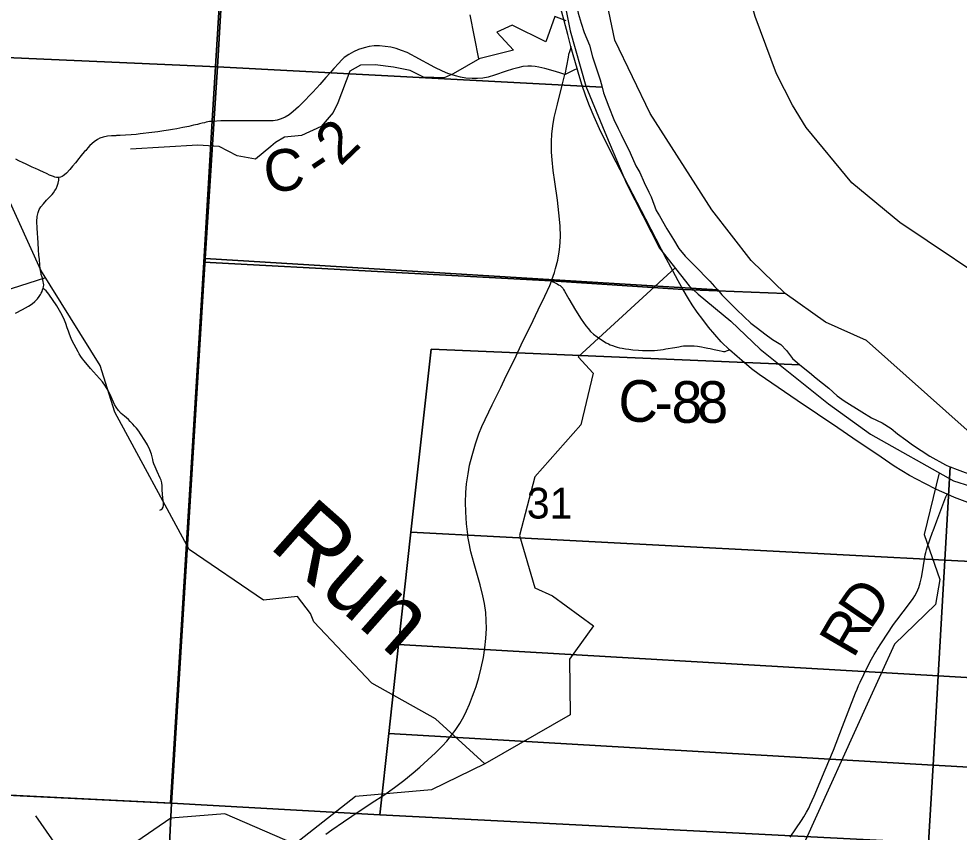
# Model space of a CAD drawing. Extents: x 0 to 34, y 0 to 22.
# Drawn here: x 5.797 to 7.078, y 15.893 to 17.002 of the extents above; entities that cross this region are included whole.
import ezdxf

# ---------------------------------------------------------------- set-up
doc = ezdxf.new("R2010")
doc.units = 0
for name, color, linetype in [('Default', 7, 'Continuous'), ('GM_X_County_Road', 7, 'Continuous'), ('GM_X_County_Road_Text', 7, 'Continuous'), ('GM_X_Interchange_Ramps', 7, 'Continuous'), ('GM_X_Major_River', 7, 'Continuous'), ('GM_X_Minor_River', 7, 'Continuous'), ('GM_X_Minor_River_Text', 7, 'Continuous'), ('GM_X_Section', 7, 'Continuous'), ('GM_X_Section_Text', 7, 'Continuous'), ('GM_X_State_Route', 7, 'Continuous'), ('GM_X_Township_Road', 7, 'Continuous'), ('SH_Text', 7, 'Continuous')]:
    doc.layers.add(name, color=color, linetype=linetype)

msp = doc.modelspace()

# ---------------------------------------------------------------- linework, layer by layer
at = {"layer": 'Default'}
for points in [[(3.9292, 16.0191), (4.6644, 15.9921), (4.9525, 15.9829), (5.4606, 15.953), (5.4699, 15.9536), (5.4787, 15.9537), (5.4884, 15.9532), (5.5007, 15.9519), (5.5038, 15.9516), (5.5088, 15.951), (5.5156, 15.9503), (5.5249, 15.9499), (5.5387, 15.9494), (5.5476, 15.9495), (5.5597, 15.9496), (5.5657, 15.9498), (5.5704, 15.951), (5.5736, 15.9525), (5.5744, 15.953), (5.6773, 15.9486), (6.0035, 15.9327), (6.0487, 16.67), (6.0603, 16.8624), (6.127, 17.9511)], [(6.127, 17.9511), (6.0603, 16.8624), (6.0487, 16.67), (6.5224, 16.6444), (6.7022, 16.6326), (6.841, 16.6271), (6.7947, 16.6724), (6.7412, 16.7413), (6.6572, 16.8728), (6.6092, 16.9726), (6.5665, 17.1768), (6.5499, 17.3472), (6.5502, 17.3673), (6.5359, 17.8831)], [(7.0892, 16.4411), (6.9521, 16.5634), (6.8963, 16.5881), (6.841, 16.6271), (6.7022, 16.6326), (6.5224, 16.6444), (6.0487, 16.67), (6.0035, 15.9327), (5.6773, 15.9486)]]:
    msp.add_lwpolyline(points, dxfattribs=at)
at = {"layer": 'GM_X_County_Road'}
for points in [[(6.5407, 16.926), (6.534, 16.9282), (6.5249, 16.9309), (6.5136, 16.9339), (6.5056, 16.9358), (6.5006, 16.9367), (6.4957, 16.9372), (6.4904, 16.9371), (6.4838, 16.9365), (6.477, 16.935), (6.4698, 16.9331), (6.4609, 16.9303), (6.4452, 16.9248), (6.4363, 16.9223), (6.4292, 16.9209), (6.4218, 16.9205), (6.4148, 16.9203), (6.4062, 16.9208), (6.3989, 16.922), (6.3917, 16.924), (6.3815, 16.9272), (6.3741, 16.9303), (6.3636, 16.9355), (6.3371, 16.9497), (6.3318, 16.9525), (6.326, 16.9556), (6.3181, 16.9587), (6.3111, 16.961), (6.3037, 16.9631), (6.2962, 16.9641), (6.2881, 16.9648), (6.281, 16.9647), (6.2741, 16.9638), (6.2675, 16.9623), (6.2597, 16.9597), (6.2529, 16.9567), (6.2464, 16.953), (6.2403, 16.9488), (6.2365, 16.9454), (6.2327, 16.9412), (6.2261, 16.9338), (6.2209, 16.928), (6.2151, 16.9215), (6.207, 16.9121), (6.2029, 16.9075), (6.1971, 16.9011), (6.1926, 16.8965), (6.1875, 16.8913), (6.1827, 16.8865), (6.178, 16.8817), (6.1708, 16.8754), (6.1651, 16.8708), (6.1599, 16.8676), (6.1544, 16.8652), (6.149, 16.8637), (6.1432, 16.8627), (6.1357, 16.8625), (6.1284, 16.8624), (6.1136, 16.8627), (6.1061, 16.8626), (6.097, 16.8626), (6.0914, 16.8627), (6.0821, 16.8625), (6.0772, 16.8625), (6.0722, 16.8624), (6.0605, 16.8619)], [(6.0605, 16.8619), (6.0594, 16.8618), (6.0566, 16.8616), (6.0543, 16.8611), (6.0521, 16.8606), (6.0496, 16.8601), (6.0467, 16.8593), (6.0431, 16.8584), (6.0401, 16.8576), (6.0377, 16.857), (6.035, 16.8565), (6.0317, 16.8557), (6.0286, 16.855), (6.0201, 16.8534), (6.0122, 16.8518), (6.0063, 16.8507), (6.0009, 16.8497), (5.9942, 16.8488), (5.9862, 16.8478), (5.9782, 16.8468), (5.9622, 16.8448), (5.9566, 16.8441), (5.9498, 16.8436), (5.942, 16.8431), (5.9349, 16.8426), (5.9299, 16.8425)], [(5.9299, 16.8425), (5.9288, 16.8424), (5.9231, 16.8422), (5.9176, 16.8418), (5.9117, 16.8405), (5.9071, 16.8389), (5.9039, 16.8373), (5.8994, 16.8342), (5.8936, 16.8288), (5.891, 16.8258), (5.888, 16.8223), (5.8863, 16.8207), (5.8835, 16.8175), (5.8815, 16.8152), (5.88, 16.8132), (5.8785, 16.8113), (5.874, 16.8056), (5.8701, 16.8007), (5.8664, 16.7965), (5.8617, 16.7915), (5.859, 16.789), (5.8572, 16.7877), (5.8557, 16.7867), (5.8535, 16.7858), (5.8514, 16.7855), (5.8501, 16.7853), (5.8481, 16.7855), (5.8456, 16.786), (5.8438, 16.7867), (5.8386, 16.7887), (5.8352, 16.7902), (5.8295, 16.7929), (5.8262, 16.7944), (5.8234, 16.7958), (5.8194, 16.7976), (5.8149, 16.7997), (5.8104, 16.8019), (5.8058, 16.804), (5.8025, 16.8056), (5.7969, 16.8083), (5.7925, 16.8105)], [(5.792, 16.6003), (5.8018, 16.6056), (5.8101, 16.6101), (5.8148, 16.6132), (5.8187, 16.6163), (5.8222, 16.6199), (5.8244, 16.623), (5.8265, 16.626), (5.8274, 16.6276), (5.8285, 16.6301), (5.8292, 16.6322), (5.8298, 16.6344), (5.8303, 16.6365), (5.8306, 16.6391), (5.8302, 16.6415), (5.8298, 16.6434), (5.8293, 16.6462), (5.8284, 16.6496), (5.8274, 16.6533), (5.827, 16.6547), (5.8266, 16.6564), (5.8263, 16.6586), (5.826, 16.661), (5.8253, 16.6664), (5.8247, 16.6736), (5.8241, 16.6796), (5.8237, 16.6867), (5.823, 16.6962), (5.8217, 16.7164), (5.8214, 16.7256), (5.8218, 16.7323), (5.8229, 16.7376), (5.8246, 16.7418), (5.8266, 16.7452), (5.8302, 16.7497), (5.8346, 16.7543), (5.84, 16.7598), (5.8421, 16.7623), (5.844, 16.7646), (5.846, 16.7676), (5.8475, 16.7699), (5.8491, 16.7734), (5.8504, 16.7775), (5.8511, 16.7819), (5.8514, 16.7855)], [(6.5226, 16.6439), (6.5276, 16.6417), (6.5304, 16.6404), (6.5323, 16.6393), (6.5344, 16.638), (6.5362, 16.6365), (6.538, 16.6344), (6.5392, 16.6326), (6.5404, 16.6306), (6.5464, 16.6202), (6.5555, 16.6045), (6.5632, 16.5923), (6.5664, 16.5876), (6.5695, 16.5832), (6.5726, 16.5794), (6.576, 16.5757), (6.5802, 16.5719), (6.5851, 16.5681), (6.5922, 16.5631), (6.5973, 16.5601), (6.6004, 16.5585), (6.6029, 16.5574), (6.6059, 16.5562), (6.6093, 16.5549), (6.6124, 16.554), (6.6156, 16.5533), (6.6191, 16.5526), (6.6237, 16.5519), (6.6283, 16.5513), (6.6334, 16.5507), (6.6412, 16.5501), (6.6468, 16.5497), (6.6516, 16.5496), (6.6553, 16.5495), (6.6594, 16.5496), (6.6632, 16.5498), (6.6671, 16.5501), (6.6712, 16.5506), (6.675, 16.5511), (6.6784, 16.5517), (6.6909, 16.5538), (6.6964, 16.5548), (6.6997, 16.5554), (6.7028, 16.5558), (6.7058, 16.556), (6.709, 16.5561), (6.7128, 16.5561), (6.7171, 16.5558), (6.7219, 16.5553), (6.727, 16.5546), (6.7314, 16.5538), (6.7356, 16.553), (6.7391, 16.5522), (6.7446, 16.5509), (6.7512, 16.5494), (6.7553, 16.5485), (6.7572, 16.5483), (6.7593, 16.5484), (6.7614, 16.549), (6.7652, 16.5505)], [(7.0428, 16.304), (7.0479, 16.3176), (7.0604, 16.35), (7.0618, 16.3537)], [(6.8482, 15.8862), (6.8635, 15.9088), (6.8668, 15.9141), (6.8705, 15.9205), (6.8733, 15.926), (6.8755, 15.9305), (6.8807, 15.9424), (6.8956, 15.9779), (6.9073, 16.0051), (6.9194, 16.0372), (6.937, 16.0828), (6.9392, 16.0881), (6.9413, 16.093), (6.9433, 16.0975), (6.9532, 16.1184), (6.9587, 16.1289), (6.9624, 16.1353), (6.9646, 16.1391), (6.9666, 16.1422), (6.9723, 16.1511), (6.989, 16.1761), (6.9932, 16.1821), (7.0106, 16.2046), (7.0156, 16.2117), (7.0179, 16.2153), (7.0205, 16.2202), (7.0233, 16.2264), (7.0254, 16.2328), (7.0272, 16.24), (7.0285, 16.2479), (7.0312, 16.2651), (7.0321, 16.271), (7.0328, 16.2744), (7.0337, 16.2777), (7.0347, 16.2809), (7.0421, 16.302), (7.0428, 16.304)]]:
    msp.add_lwpolyline(points, dxfattribs=at)
at = {"layer": 'GM_X_Interchange_Ramps'}
msp.add_lwpolyline([(6.5493, 16.9638), (6.548, 16.9596), (6.5471, 16.9568), (6.5461, 16.9531), (6.5453, 16.9493), (6.5407, 16.926)], dxfattribs=at)
at = {"layer": 'GM_X_Major_River'}
for points in [[(6.4976, 17.8073), (6.4924, 17.6107), (6.4898, 17.5078), (6.4973, 17.4197), (6.5019, 17.3214), (6.514, 17.2114), (6.5258, 17.1009), (6.5409, 17.0216), (6.5482, 16.9852), (6.5697, 16.9098), (6.5979, 16.8416), (6.625, 16.7771), (6.67, 16.6892), (6.7102, 16.6378), (6.7228, 16.6264), (6.7671, 16.5894), (6.807, 16.5512), (6.9003, 16.4768), (6.9575, 16.4357), (7.0708, 16.372), (7.0939, 16.3645)], [(7.1477, 16.6232), (6.9976, 16.724), (6.932, 16.778), (6.87, 16.8537), (6.8514, 16.884), (6.8293, 16.9268), (6.8003, 17.0049), (6.7845, 17.0602), (6.7543, 17.1645), (6.7441, 17.2389), (6.7426, 17.2521), (6.7301, 17.3527), (6.7197, 17.489), (6.7149, 17.5588), (6.7178, 17.5835)]]:
    msp.add_lwpolyline(points, dxfattribs=at)
at = {"layer": 'GM_X_Minor_River'}
for points in [[(6.5429, 16.9987), (6.5271, 17.0046), (6.515, 16.9704), (6.4692, 16.9931), (6.4484, 16.9834), (6.4708, 16.959), (6.4235, 16.9471), (6.4121, 17.007)], [(6.4252, 16.9476), (6.3887, 16.9268), (6.3765, 16.9211), (6.3481, 16.9222), (6.3299, 16.931), (6.3072, 16.9359), (6.2825, 16.9389), (6.2624, 16.9385), (6.2477, 16.9305), (6.2313, 16.8871), (6.2253, 16.8738), (6.2086, 16.8548), (6.182, 16.8426), (6.1589, 16.8403), (6.1464, 16.8331), (6.14, 16.8277), (6.1191, 16.8106), (6.0945, 16.8148), (6.0698, 16.8277), (6.0406, 16.8295), (5.9489, 16.8241)], [(6.6911, 16.6622), (6.559, 16.5411), (6.5794, 16.5185), (6.5629, 16.4485), (6.5001, 16.3773), (6.4791, 16.2974), (6.4998, 16.2263), (6.5242, 16.2151), (6.5798, 16.1742), (6.5474, 16.1291), (6.5484, 16.0532), (6.4319, 15.9861), (6.3647, 16.0474), (6.2779, 16.096), (6.199, 16.1799), (6.1942, 16.1913), (6.1765, 16.2143), (6.1302, 16.2093), (6.0287, 16.2782), (5.9276, 16.4656), (5.9077, 16.5292), (5.8267, 16.659), (5.7806, 16.7611)], [(5.8331, 16.6488), (5.7289, 16.6153), (5.6643, 16.5676), (5.5809, 16.5244), (5.4957, 16.4504), (5.3153, 16.3717), (5.1891, 16.3569), (5.13, 16.378), (5.1094, 16.4116), (5.0356, 16.4277), (4.9613, 16.3871), (4.8576, 16.3065), (4.7856, 16.293), (4.6967, 16.3901), (4.6197, 16.4107), (4.6082, 16.42), (4.5364, 16.4558)], [(7.0512, 16.383), (7.0307, 16.2989), (7.052, 16.2373), (7.046, 16.2034), (6.9901, 16.1494), (6.9529, 16.0675), (6.8687, 15.8822), (6.8299, 15.7479), (6.7922, 15.6967), (6.7077, 15.6246), (6.6722, 15.5286), (6.5634, 15.372), (6.5491, 15.356)], [(6.4319, 15.9861), (6.3591, 15.951), (6.2556, 15.9417), (6.1729, 15.8768), (6.0775, 15.9181), (6.0039, 15.9121), (5.8952, 15.8379), (5.8596, 15.8588), (5.8201, 15.9154)]]:
    msp.add_lwpolyline(points, dxfattribs=at)
at = {"layer": 'GM_X_Section'}
for points in [[(5.0782, 18.0036), (6.1294, 17.9583), (6.1188, 17.7931), (6.0808, 17.1618), (6.0674, 16.9363), (5.0081, 16.9831)], [(6.5357, 17.1413), (6.5377, 17.1323), (6.5407, 17.116), (6.5435, 17.0974), (6.5454, 17.0853), (6.5458, 17.0762), (6.5481, 17.0599), (6.5528, 17.0383), (6.5574, 17.0194), (6.5589, 17.0092), (6.5631, 16.9956), (6.5673, 16.9831), (6.5746, 16.9657), (6.5788, 16.9498), (6.5846, 16.932), (6.5892, 16.9187), (6.5918, 16.9087), (6.0674, 16.9363), (6.0808, 17.1618)], [(6.0674, 16.9363), (6.0506, 16.6748), (6.0049, 15.9328), (4.9568, 15.9843), (4.9447, 15.9846), (5.0081, 16.9831)], [(6.5918, 16.9087), (6.5938, 16.901), (6.601, 16.8817), (6.6079, 16.8646), (6.6137, 16.8521), (6.6175, 16.8438), (6.6301, 16.8189), (6.6377, 16.8015), (6.643, 16.792), (6.6491, 16.7784), (6.6552, 16.7655), (6.6587, 16.7591), (6.6656, 16.7406), (6.6698, 16.733), (6.68, 16.7156), (6.6888, 16.7009), (6.6964, 16.6888), (6.7048, 16.6782), (6.7177, 16.6653), (6.7386, 16.6442), (6.7451, 16.637), (6.7494, 16.6321), (6.0506, 16.6748), (6.0674, 16.9363)], [(6.7494, 16.6321), (6.755, 16.6257), (6.7755, 16.6049), (6.7942, 16.5868), (6.8033, 16.58), (6.8135, 16.5721), (6.8238, 16.5645), (6.8352, 16.5578), (6.8432, 16.5498), (6.8512, 16.5389), (6.8613, 16.5301), (6.3587, 16.5515), (6.3312, 16.3019), (6.3143, 16.1489), (6.3009, 16.0274), (6.2887, 15.9168), (6.0049, 15.9328), (6.0506, 16.6748)], [(6.8613, 16.5301), (6.8743, 16.5196), (6.8835, 16.5117), (6.9006, 16.4981), (6.9123, 16.4876), (6.9218, 16.4808), (6.9458, 16.4661), (6.959, 16.4578), (6.9735, 16.451), (6.9856, 16.4435), (6.9944, 16.4359), (7.0058, 16.428), (7.0149, 16.4209), (7.0384, 16.4058), (7.0597, 16.3937), (7.0617, 16.3929), (7.0662, 16.3911), (7.0589, 16.264), (6.3312, 16.3019), (6.3587, 16.5515)], [(7.0589, 16.264), (7.0662, 16.3911), (7.0756, 16.3873), (7.0988, 16.3787), (7.1136, 16.3735), (7.134, 16.3697), (7.1496, 16.366), (7.1659, 16.3608), (7.1845, 16.351), (7.2046, 16.3401), (7.2316, 16.325), (7.2581, 16.3111), (7.2729, 16.3032), (7.2889, 16.2926), (7.32, 16.2757), (7.3352, 16.2685), (7.3439, 16.2625), (7.3565, 16.2534), (7.3629, 16.2482)], [(6.3312, 16.3019), (7.0589, 16.264), (7.0498, 16.1061), (6.3143, 16.1489)], [(7.0589, 16.264), (7.3629, 16.2482), (7.3747, 16.2387), (7.3956, 16.224), (7.4153, 16.2108), (7.4328, 16.1988), (7.4545, 16.1814), (7.4742, 16.1659), (7.4875, 16.155), (7.5008, 16.1429), (7.5194, 16.1244), (7.5312, 16.115), (7.5453, 16.1048), (7.5586, 16.0935), (7.5704, 16.0825), (7.5767, 16.0755), (7.0498, 16.1061)], [(7.0498, 16.1061), (7.0427, 15.9845), (6.3009, 16.0274), (6.3143, 16.1489)], [(7.5767, 16.0755), (7.586, 16.0652), (7.6008, 16.0512), (7.6137, 16.0395), (7.6278, 16.0236), (7.6468, 16.0021), (7.6563, 15.9919), (7.6662, 15.9794), (7.6734, 15.9704), (7.6833, 15.9598), (7.6919, 15.9479), (7.0427, 15.9845), (7.0498, 16.1061)], [(6.3009, 16.0274), (7.0427, 15.9845), (7.0366, 15.8787), (6.2887, 15.9168)], [(4.9568, 15.9843), (6.0049, 15.9328), (5.9932, 15.6936), (5.9754, 15.4391), (5.9587, 15.1787), (5.9407, 14.9107), (5.9405, 14.9074), (4.8777, 14.9601)], [(7.0427, 15.9845), (7.6919, 15.9479), (7.7031, 15.9322), (7.7119, 15.9182), (7.7344, 15.885), (7.7427, 15.8732), (7.7526, 15.86), (7.7602, 15.8494), (7.772, 15.8408), (7.2798, 15.8662), (7.0366, 15.8787)], [(6.0049, 15.9328), (6.2887, 15.9168), (7.0366, 15.8787), (7.0224, 15.6312), (5.9932, 15.6936)]]:
    msp.add_lwpolyline(points, close=True, dxfattribs=at)
at = {"layer": 'GM_X_State_Route'}
msp.add_line((6.5226, 16.6439), (6.5233, 16.6458), dxfattribs=at)
for points in [[(6.5493, 16.9638), (6.5448, 16.9804), (6.5399, 16.999), (6.5303, 17.035)], [(6.7024, 16.6321), (6.6952, 16.6445), (6.6879, 16.6581), (6.6796, 16.6741), (6.6515, 16.7288), (6.6279, 16.774), (6.6109, 16.8065), (6.5987, 16.8303), (6.5883, 16.8515), (6.581, 16.868), (6.5747, 16.8829), (6.5697, 16.8963), (6.5642, 16.9122), (6.559, 16.9289), (6.5575, 16.9341), (6.5523, 16.9528), (6.5493, 16.9638)], [(6.5233, 16.6458), (6.525, 16.6507), (6.5268, 16.656), (6.5284, 16.6612), (6.5312, 16.6726), (6.5333, 16.684), (6.5341, 16.6911), (6.5348, 16.7051), (6.5346, 16.7192), (6.5337, 16.7287), (6.5307, 16.7547), (6.5272, 16.7797), (6.5251, 16.795), (6.5235, 16.8096), (6.5227, 16.8201), (6.5226, 16.8345), (6.5232, 16.8445), (6.5245, 16.8558), (6.5265, 16.8671), (6.5308, 16.8852), (6.5372, 16.9111), (6.5407, 16.926), (6.5473, 16.9291), (6.5537, 16.9322), (6.5575, 16.9341)], [(6.4089, 16.2959), (6.4085, 16.2989), (6.4068, 16.3132), (6.406, 16.3295), (6.4057, 16.3424), (6.4062, 16.3562), (6.4071, 16.3677), (6.409, 16.3813), (6.4111, 16.3931), (6.4144, 16.4066), (6.419, 16.4222), (6.4237, 16.4358), (6.428, 16.4461), (6.4419, 16.4756), (6.4535, 16.4992), (6.4611, 16.5149), (6.4721, 16.5375), (6.4816, 16.5573), (6.4892, 16.5731), (6.4939, 16.5829), (6.5047, 16.6049), (6.5137, 16.6235), (6.5204, 16.6384), (6.5226, 16.6439)], [(7.0618, 16.3537), (7.0475, 16.3603), (7.0314, 16.3684), (7.0107, 16.3793), (6.9896, 16.3921), (6.972, 16.404), (6.9334, 16.4302), (6.913, 16.4441), (6.8576, 16.4814), (6.8059, 16.5169), (6.7955, 16.5248), (6.7852, 16.5331), (6.7757, 16.5413), (6.7652, 16.5505), (6.7542, 16.5616), (6.7453, 16.5713), (6.7369, 16.5815), (6.7288, 16.592), (6.7214, 16.602), (6.7146, 16.6117), (6.7093, 16.6202), (6.7024, 16.6321)], [(7.1147, 16.3337), (7.1109, 16.3349), (7.0997, 16.3388), (7.0828, 16.3451), (7.0718, 16.3494), (7.0618, 16.3537)], [(6.215, 15.8906), (6.2233, 15.8964), (6.2391, 15.9073), (6.2507, 15.915), (6.2782, 15.9334), (6.294, 15.9437), (6.3089, 15.954), (6.3217, 15.9635), (6.334, 15.9741), (6.3433, 15.9818), (6.3541, 15.9918), (6.3645, 16.0014), (6.374, 16.011), (6.38, 16.0171), (6.3866, 16.0253), (6.3915, 16.0316), (6.3977, 16.0412), (6.4033, 16.0507), (6.407, 16.0585), (6.4109, 16.0678), (6.4152, 16.0783), (6.4174, 16.0846), (6.42, 16.0917), (6.4237, 16.104), (6.4269, 16.117), (6.4299, 16.1312), (6.432, 16.1443), (6.4334, 16.1571), (6.4342, 16.1707), (6.4339, 16.1814), (6.4331, 16.1927), (6.4316, 16.2046), (6.4292, 16.2154), (6.4255, 16.2301), (6.4175, 16.2588), (6.413, 16.275), (6.41, 16.2891), (6.4089, 16.2959)]]:
    msp.add_lwpolyline(points, dxfattribs=at)
at = {"layer": 'GM_X_Township_Road'}
msp.add_lwpolyline([(5.989, 16.3318), (5.9907, 16.3327), (5.9922, 16.3338), (5.9934, 16.336), (5.994, 16.3384), (5.994, 16.3408), (5.9935, 16.345), (5.9931, 16.3482), (5.9925, 16.3543), (5.9922, 16.3592), (5.9919, 16.3651), (5.9916, 16.3694), (5.9908, 16.3729), (5.9893, 16.3757), (5.9853, 16.3846), (5.9826, 16.3912), (5.9809, 16.3951), (5.98, 16.3979), (5.9792, 16.4011), (5.9774, 16.4084), (5.9753, 16.4144), (5.9719, 16.4211), (5.9686, 16.4268), (5.9627, 16.4359), (5.9601, 16.4395), (5.9572, 16.4437), (5.9545, 16.4465), (5.952, 16.4491), (5.9484, 16.453), (5.946, 16.4556), (5.9408, 16.46), (5.9362, 16.4639), (5.9327, 16.4676), (5.9292, 16.4724), (5.927, 16.476), (5.9212, 16.4898), (5.9185, 16.4952), (5.9151, 16.5008), (5.9106, 16.5068), (5.8944, 16.5252), (5.8856, 16.5356), (5.8836, 16.5384), (5.8812, 16.5415), (5.8791, 16.545), (5.8774, 16.5479), (5.872, 16.5576), (5.87, 16.5619), (5.8681, 16.5661), (5.866, 16.5717), (5.8643, 16.576), (5.8628, 16.5807), (5.8609, 16.5866), (5.8583, 16.593), (5.8542, 16.601), (5.8485, 16.6104), (5.8377, 16.6265), (5.8339, 16.6307), (5.8318, 16.6329), (5.8298, 16.6344)], dxfattribs=at)
at = {"layer": 'SH_Text'}
msp.add_lwpolyline([(7.0892, 16.4411), (6.9521, 16.5634), (6.8963, 16.5881), (6.841, 16.6271), (6.7947, 16.6724), (6.7412, 16.7413), (6.6572, 16.8728), (6.6092, 16.9726), (6.5665, 17.1768), (6.5499, 17.3472), (6.5502, 17.3673), (6.5359, 17.8831)], dxfattribs=at)

# ---------------------------------------------------------------- texts
at = {"layer": 'GM_X_County_Road_Text'}
for s, rotation, p in [('2', 43.8461, (6.2348, 16.7996)), ('C', 7.704, (6.1345, 16.7637)), ('-', 33.7753, (6.2069, 16.7798)), ('C', 355.9044, (6.612, 16.4545)), ('8', 359.9506, (6.6863, 16.4511)), ('8', 359.9992, (6.7214, 16.451)), ('-', 0.0272, (6.663, 16.451)), ('D', 55.5613, (6.9571, 16.1679)), ('R', 59.6882, (6.9341, 16.1286))]:
    msp.add_text(s, height=0.0568, rotation=rotation, dxfattribs=at).set_placement(p)
at = {"layer": 'GM_X_Minor_River_Text'}
msp.add_text('Run', height=0.0947, rotation=318.511, dxfattribs=at).set_placement((6.1357, 16.2826))
at = {"layer": 'GM_X_Section_Text'}
msp.add_text('31', height=0.04186, rotation=0, dxfattribs=at).set_placement((6.4891, 16.3206))

doc.saveas('drawing.dxf')
